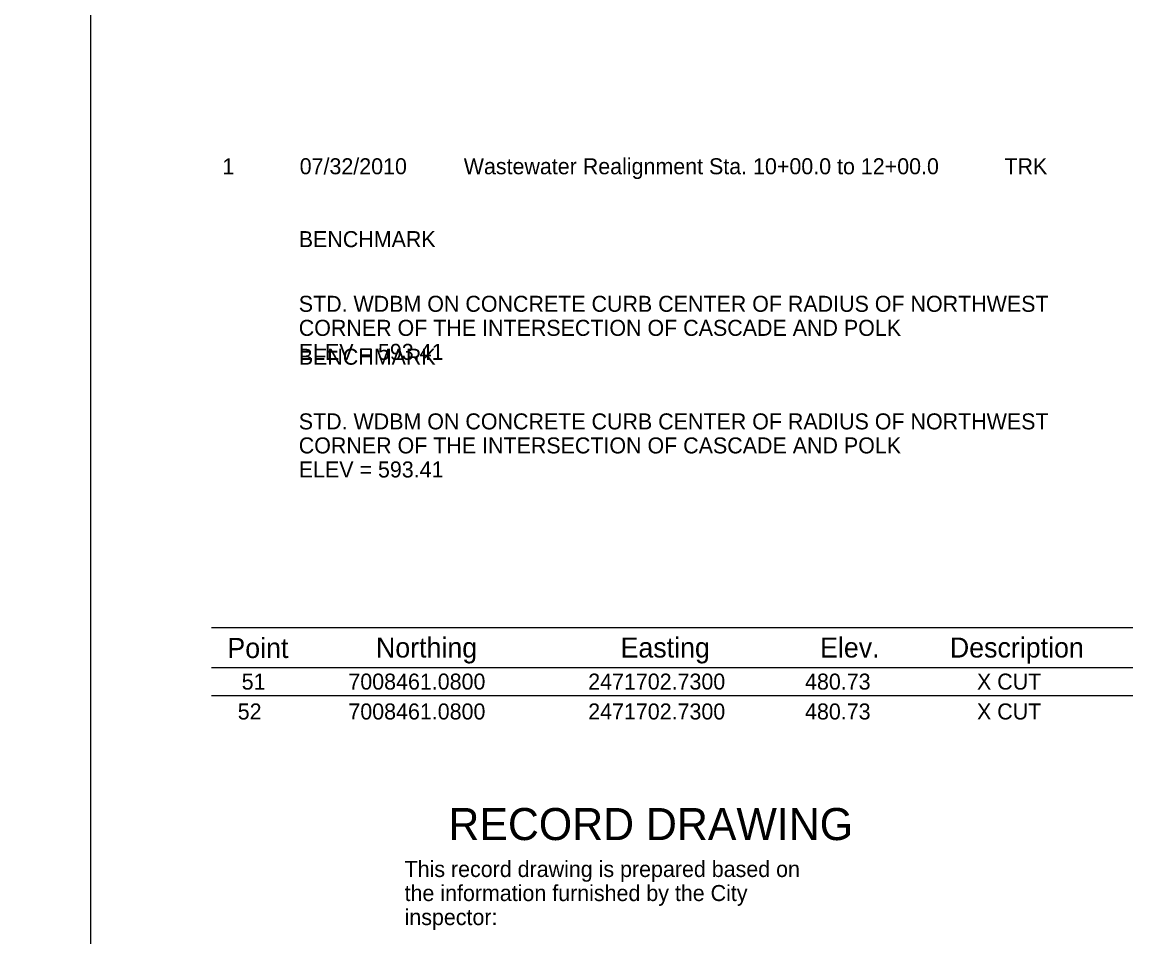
# Model space of a CAD drawing. Extents: x -3549 to -1863, y -2443 to -1503.
# Drawn here: x -2146.1 to -1868.8, y -2209.9 to -1981.6 of the extents above; entities that cross this region are included whole.
import ezdxf

# ---------------------------------------------------------------- set-up
doc = ezdxf.new("R2010")
doc.units = 0
for name, color, linetype in [('G_BORDER', 7, 'Continuous'), ('G_SHEET_EDGE', 7, 'Continuous'), ('G_SIGNATURE BLOCK', 7, 'Continuous')]:
    doc.layers.add(name, color=color, linetype=linetype)

msp = doc.modelspace()

# ---------------------------------------------------------------- linework, layer by layer
at = {"layer": 'G_BORDER'}
for p, q in [((-2098.81, -2132.68), (-1868.81, -2132.68)), ((-2098.81, -2142.68), (-1868.81, -2142.68)), ((-2098.81, -2149.68), (-1868.81, -2149.68))]:
    msp.add_line(p, q, dxfattribs=at)
at = {"layer": 'G_SHEET_EDGE'}
msp.add_lwpolyline([(-2129, -1512.26), (-3549, -1512.26), (-3549, -2432.26), (-2129, -2432.26)], close=True, dxfattribs=at)

# ---------------------------------------------------------------- texts
at = {"layer": 'G_BORDER'}
for s, height, p in [('1', 4, (-2096.11, -2019.55)), ('07/32/2010', 4, (-2076.82, -2019.55)), ('Wastewater Realignment Sta. 10+00.0 to 12+00.0', 4, (-2035.86, -2019.55)), ('TRK', 4, (-1900.85, -2019.55)), ('BENCHMARK', 4, (-2077.05, -2037.74)), ('STD. WDBM ON CONCRETE CURB CENTER OF RADIUS OF NORTHWEST', 4, (-2077.05, -2053.88)), ('CORNER OF THE INTERSECTION OF CASCADE AND POLK', 4, (-2077.05, -2059.88)), ('ELEV = 593.41', 4, (-2077.05, -2065.88)), ('BENCHMARK', 4, (-2077.05, -2067.09)), ('STD. WDBM ON CONCRETE CURB CENTER OF RADIUS OF NORTHWEST', 4, (-2077.05, -2083.23)), ('CORNER OF THE INTERSECTION OF CASCADE AND POLK', 4, (-2077.05, -2089.23)), ('ELEV = 593.41', 4, (-2077.05, -2095.23)), ('Point', 5, (-2094.88, -2140.29)), ('Northing', 5, (-2057.78, -2140.18)), ('Easting', 5, (-1996.71, -2140.18)), ('Elev.', 5, (-1946.89, -2140.18)), ('Description', 5, (-1914.48, -2140.18)), ('51', 4, (-2091.3, -2148.18)), ('7008461.0800', 4, (-2064.66, -2148.18)), ('2471702.7300', 4, (-2004.78, -2148.18)), ('480.73', 4, (-1950.64, -2148.18)), ('X CUT', 4, (-1907.71, -2148.18)), ('52', 4, (-2092.29, -2155.64)), ('7008461.0800', 4, (-2064.66, -2155.64)), ('2471702.7300', 4, (-2004.78, -2155.64)), ('480.73', 4, (-1950.64, -2155.64)), ('X CUT', 4, (-1907.71, -2155.64))]:
    msp.add_text(s, height=height, dxfattribs=at).set_placement(p)
at = {"layer": 'G_SIGNATURE BLOCK'}
msp.add_text('RECORD DRAWING', height=8, rotation=360, dxfattribs=at).set_placement((-2039.69, -2185.74))
for s, p in [('This record drawing is prepared based on', (-2050.63, -2194.96)), ('the information furnished by the City', (-2050.63, -2200.96)), ('inspector:', (-2050.63, -2206.96))]:
    msp.add_text(s, height=4, dxfattribs=at).set_placement(p)

doc.saveas('drawing.dxf')
